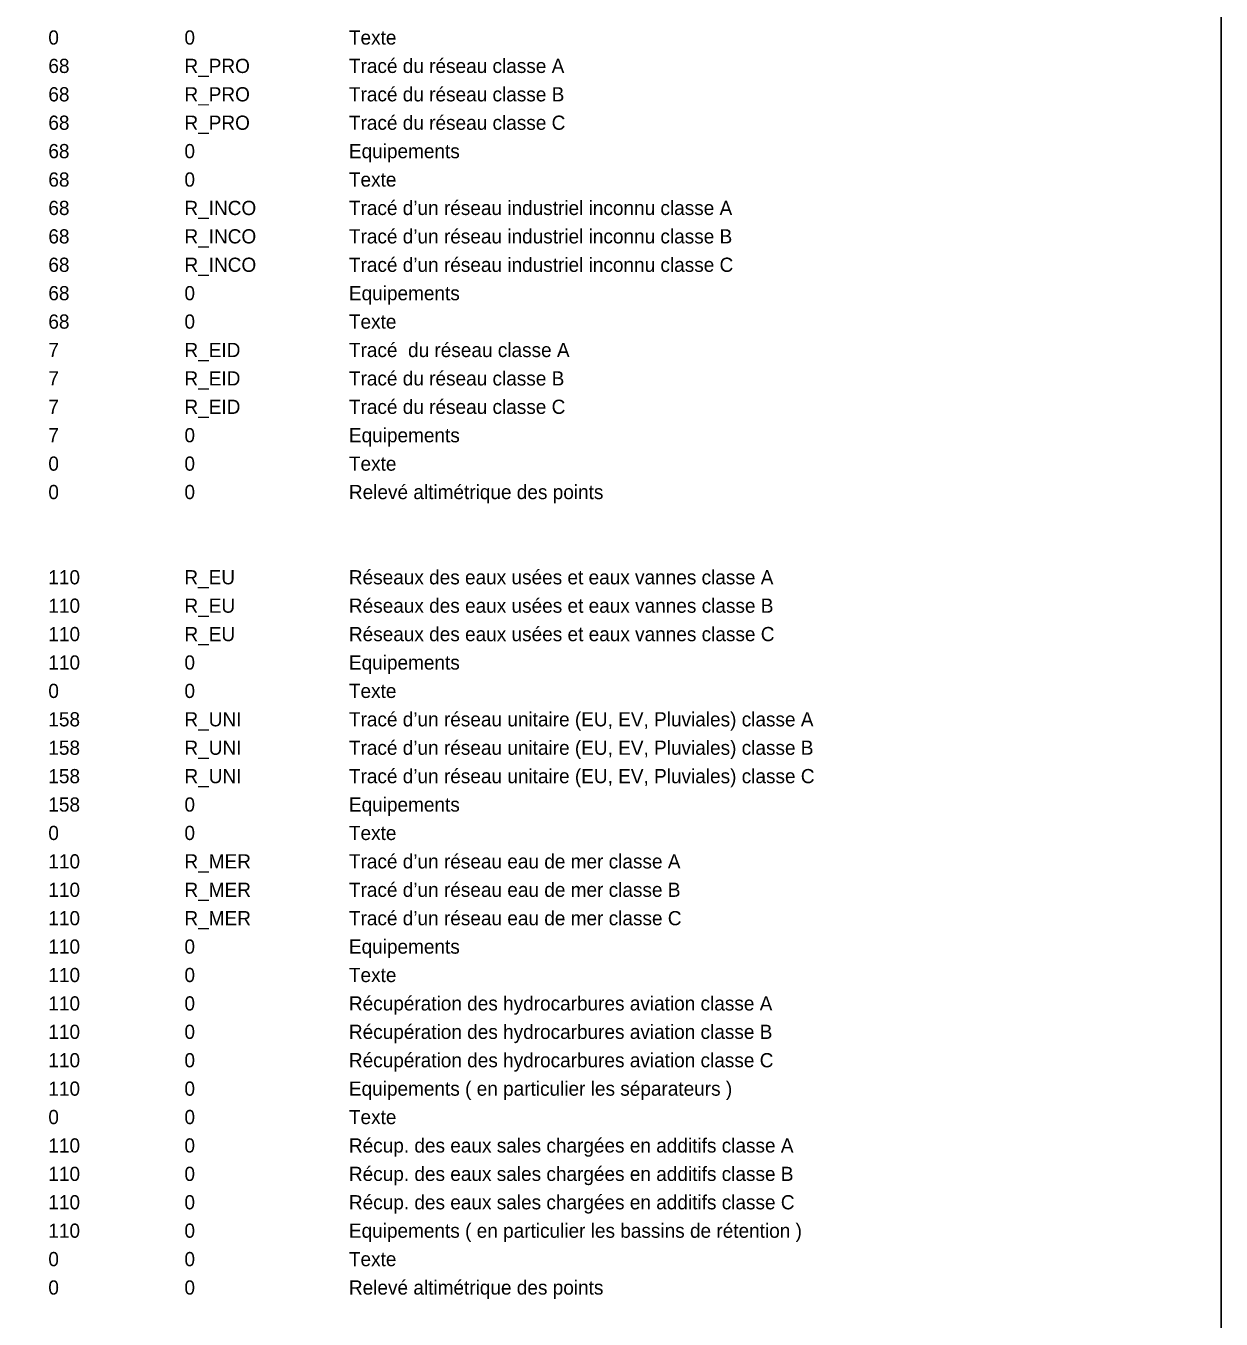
# Model space of a CAD drawing. Extents: x -60 to 214, y -380 to -21.
# Drawn here: x 72.77 to 114.84, y -201.47 to -155.95 of the extents above; entities that cross this region are included whole.
import ezdxf

# ---------------------------------------------------------------- set-up
doc = ezdxf.new("R2010")
doc.units = 0
for name, color, linetype in [('Default', 7, 'Continuous'), ('R_ES_EAU_SALE_ALT_POINT', 7, 'Continuous'), ('R_ES_EU_CANALISATION_CL_A', 7, 'Continuous'), ('R_ES_EU_CANALISATION_CL_B', 7, 'Continuous'), ('R_ES_EU_CANALISATION_CL_C', 7, 'Continuous'), ('R_ES_EU_EQUIP', 7, 'Continuous'), ('R_ES_EU_TEXTE', 7, 'Continuous'), ('R_ES_HYDROCARB_CANA_CL_A', 7, 'Continuous'), ('R_ES_HYDROCARB_CANA_CL_B', 7, 'Continuous'), ('R_ES_HYDROCARB_CANA_CL_C', 7, 'Continuous'), ('R_ES_HYDROCARB_EQUIP', 7, 'Continuous'), ('R_ES_HYDROCARB_TEXTE', 7, 'Continuous'), ('R_ES_INCENDIE_CANA_CL_A', 7, 'Continuous'), ('R_ES_INCENDIE_CANA_CL_B', 7, 'Continuous'), ('R_ES_INCENDIE_CANA_CL_C', 7, 'Continuous'), ('R_ES_INCENDIE_EQUIP', 7, 'Continuous'), ('R_ES_INCENDIE_TEXTE', 7, 'Continuous'), ('R_ES_MER_CANALISATION_CL_A', 7, 'Continuous'), ('R_ES_MER_CANALISATION_CL_B', 7, 'Continuous'), ('R_ES_MER_CANALISATION_CL_C', 7, 'Continuous'), ('R_ES_MER_EQUIP', 7, 'Continuous'), ('R_ES_MER_TEXTE', 7, 'Continuous'), ('R_ES_UNITAIRE_CANALISATION_CL_A', 7, 'Continuous'), ('R_ES_UNITAIRE_CANALISATION_CL_B', 7, 'Continuous'), ('R_ES_UNITAIRE_CANALISATION_CL_C', 7, 'Continuous'), ('R_ES_UNITAIRE_EQUIP', 7, 'Continuous'), ('R_ES_UNITAIRE_TEXTE', 7, 'Continuous'), ('R_IND_ALT_POINT', 7, 'Continuous'), ('R_IND_EAU_DEMINERALISEE_CANALISATION_CL_A', 7, 'Continuous'), ('R_IND_EAU_DEMINERALISEE_CANALISATION_CL_B', 7, 'Continuous'), ('R_IND_EAU_DEMINERALISEE_CANALISATION_CL_C', 7, 'Continuous'), ('R_IND_EAU_DEMINERALISEE_EQUIP', 7, 'Continuous'), ('R_IND_EAU_DEMINERALISEE_TEXTE', 7, 'Continuous'), ('R_IND_HYDROCARBURE_TEXTE', 7, 'Continuous'), ('R_IND_INDUS_INCON_CANALISATION_CL_A', 7, 'Continuous'), ('R_IND_INDUS_INCON_CANALISATION_CL_B', 7, 'Continuous'), ('R_IND_INDUS_INCON_CANALISATION_CL_C', 7, 'Continuous'), ('R_IND_INDUS_INCON_EQUIP', 7, 'Continuous'), ('R_IND_INDUS_INCON_TEXTE', 7, 'Continuous'), ('R_IND_PROPANE_CANALISATION_CL_A', 7, 'Continuous'), ('R_IND_PROPANE_CANALISATION_CL_B', 7, 'Continuous'), ('R_IND_PROPANE_CANALISATION_CL_C', 7, 'Continuous'), ('R_IND_PROPANE_EQUIP', 7, 'Continuous'), ('R_IND_PROPANE_TEXTE', 7, 'Continuous')]:
    doc.layers.add(name, color=color, linetype=linetype)

msp = doc.modelspace()

# ---------------------------------------------------------------- linework, layer by layer
at = {"layer": 'Default'}
msp.add_lwpolyline([(114.838, -25.727), (33.073, -25.727), (33.073, -380.216), (114.838, -380.216)], close=True, dxfattribs=at)

# ---------------------------------------------------------------- texts
at = {"layer": 'R_ES_EAU_SALE_ALT_POINT'}
for s, p in [('0 ', (73.561, -200.61)), ('0 ', (78.351, -200.61)), ('Relevé altimétrique des points ', (84.14, -200.61))]:
    msp.add_text(s, height=0.5, dxfattribs=at).set_placement(p)
at = {"layer": 'R_ES_EU_CANALISATION_CL_A'}
for s, p in [('110 ', (73.559, -175.61)), ('R_EU ', (78.348, -175.61)), ('Réseaux des eaux usées et eaux vannes classe A ', (84.138, -175.61))]:
    msp.add_text(s, height=0.5, dxfattribs=at).set_placement(p)
at = {"layer": 'R_ES_EU_CANALISATION_CL_B'}
for s, p in [('110 ', (73.561, -176.61)), ('R_EU ', (78.351, -176.61)), ('Réseaux des eaux usées et eaux vannes classe B ', (84.14, -176.61))]:
    msp.add_text(s, height=0.5, dxfattribs=at).set_placement(p)
at = {"layer": 'R_ES_EU_CANALISATION_CL_C'}
for s, p in [('Réseaux des eaux usées et eaux vannes classe C ', (84.14, -177.61)), ('110 ', (73.561, -177.61)), ('R_EU ', (78.351, -177.61))]:
    msp.add_text(s, height=0.5, dxfattribs=at).set_placement(p)
at = {"layer": 'R_ES_EU_EQUIP'}
for s, p in [('110 ', (73.561, -178.61)), ('0 ', (78.351, -178.61)), ('Equipements ', (84.14, -178.61))]:
    msp.add_text(s, height=0.5, dxfattribs=at).set_placement(p)
at = {"layer": 'R_ES_EU_TEXTE'}
for s, p in [('0', (73.561, -179.61)), ('0 ', (78.351, -179.61)), ('Texte ', (84.14, -179.61))]:
    msp.add_text(s, height=0.5, dxfattribs=at).set_placement(p)
at = {"layer": 'R_ES_HYDROCARB_CANA_CL_A'}
for s, p in [('110 ', (73.561, -190.61)), ('0 ', (78.351, -190.61)), ('Récupération des hydrocarbures aviation classe A ', (84.14, -190.61))]:
    msp.add_text(s, height=0.5, dxfattribs=at).set_placement(p)
at = {"layer": 'R_ES_HYDROCARB_CANA_CL_B'}
for s, p in [('110 ', (73.561, -191.61)), ('0 ', (78.351, -191.61)), ('Récupération des hydrocarbures aviation classe B ', (84.14, -191.61))]:
    msp.add_text(s, height=0.5, dxfattribs=at).set_placement(p)
at = {"layer": 'R_ES_HYDROCARB_CANA_CL_C'}
for s, p in [('110 ', (73.561, -192.61)), ('0 ', (78.351, -192.61)), ('Récupération des hydrocarbures aviation classe C ', (84.14, -192.61))]:
    msp.add_text(s, height=0.5, dxfattribs=at).set_placement(p)
at = {"layer": 'R_ES_HYDROCARB_EQUIP'}
for s, p in [('110 ', (73.561, -193.61)), ('0 ', (78.351, -193.61)), ('Equipements ( en particulier les séparateurs )  ', (84.14, -193.61))]:
    msp.add_text(s, height=0.5, dxfattribs=at).set_placement(p)
at = {"layer": 'R_ES_HYDROCARB_TEXTE'}
for s, p in [('0', (73.561, -194.61)), ('0 ', (78.351, -194.61)), ('Texte ', (84.14, -194.61))]:
    msp.add_text(s, height=0.5, dxfattribs=at).set_placement(p)
at = {"layer": 'R_ES_INCENDIE_CANA_CL_A'}
for s, p in [('110 ', (73.561, -195.61)), ('0 ', (78.351, -195.61)), ('Récup. des eaux sales chargées en additifs classe A ', (84.14, -195.61))]:
    msp.add_text(s, height=0.5, dxfattribs=at).set_placement(p)
at = {"layer": 'R_ES_INCENDIE_CANA_CL_B'}
for s, p in [('110 ', (73.561, -196.61)), ('0 ', (78.351, -196.61)), ('Récup. des eaux sales chargées en additifs classe B ', (84.14, -196.61))]:
    msp.add_text(s, height=0.5, dxfattribs=at).set_placement(p)
at = {"layer": 'R_ES_INCENDIE_CANA_CL_C'}
for s, p in [('110 ', (73.561, -197.61)), ('0 ', (78.351, -197.61)), ('Récup. des eaux sales chargées en additifs classe C ', (84.14, -197.61))]:
    msp.add_text(s, height=0.5, dxfattribs=at).set_placement(p)
at = {"layer": 'R_ES_INCENDIE_EQUIP'}
for s, p in [('110 ', (73.561, -198.61)), ('0 ', (78.351, -198.61)), ('Equipements ( en particulier les bassins de rétention ) ', (84.14, -198.61))]:
    msp.add_text(s, height=0.5, dxfattribs=at).set_placement(p)
at = {"layer": 'R_ES_INCENDIE_TEXTE'}
for s, p in [('0', (73.561, -199.61)), ('0 ', (78.351, -199.61)), ('Texte ', (84.14, -199.61))]:
    msp.add_text(s, height=0.5, dxfattribs=at).set_placement(p)
at = {"layer": 'R_ES_MER_CANALISATION_CL_A'}
for s, p in [('110 ', (73.561, -185.61)), ('R_MER ', (78.351, -185.61)), ('Tracé d’un réseau eau de mer classe A ', (84.14, -185.61))]:
    msp.add_text(s, height=0.5, dxfattribs=at).set_placement(p)
at = {"layer": 'R_ES_MER_CANALISATION_CL_B'}
for s, p in [('110 ', (73.561, -186.61)), ('R_MER ', (78.351, -186.61)), ('Tracé d’un réseau eau de mer classe B ', (84.14, -186.61))]:
    msp.add_text(s, height=0.5, dxfattribs=at).set_placement(p)
at = {"layer": 'R_ES_MER_CANALISATION_CL_C'}
for s, p in [('Tracé d’un réseau eau de mer classe C ', (84.14, -187.61)), ('110 ', (73.561, -187.61)), ('R_MER ', (78.351, -187.61))]:
    msp.add_text(s, height=0.5, dxfattribs=at).set_placement(p)
at = {"layer": 'R_ES_MER_EQUIP'}
for s, p in [('110 ', (73.561, -188.61)), ('0 ', (78.351, -188.61)), ('Equipements ', (84.14, -188.61))]:
    msp.add_text(s, height=0.5, dxfattribs=at).set_placement(p)
at = {"layer": 'R_ES_MER_TEXTE'}
for s, p in [('110 ', (73.561, -189.61)), ('0 ', (78.351, -189.61)), ('Texte ', (84.14, -189.61))]:
    msp.add_text(s, height=0.5, dxfattribs=at).set_placement(p)
at = {"layer": 'R_ES_UNITAIRE_CANALISATION_CL_A'}
for s, p in [('158 ', (73.561, -180.61)), ('R_UNI ', (78.351, -180.61)), ('Tracé d’un réseau unitaire (EU, EV, Pluviales) classe A ', (84.14, -180.61))]:
    msp.add_text(s, height=0.5, dxfattribs=at).set_placement(p)
at = {"layer": 'R_ES_UNITAIRE_CANALISATION_CL_B'}
for s, p in [('158 ', (73.561, -181.61)), ('R_UNI ', (78.351, -181.61)), ('Tracé d’un réseau unitaire (EU, EV, Pluviales) classe B ', (84.14, -181.61))]:
    msp.add_text(s, height=0.5, dxfattribs=at).set_placement(p)
at = {"layer": 'R_ES_UNITAIRE_CANALISATION_CL_C'}
for s, p in [('Tracé d’un réseau unitaire (EU, EV, Pluviales) classe C ', (84.14, -182.61)), ('158 ', (73.561, -182.61)), ('R_UNI ', (78.351, -182.61))]:
    msp.add_text(s, height=0.5, dxfattribs=at).set_placement(p)
at = {"layer": 'R_ES_UNITAIRE_EQUIP'}
for s, p in [('158 ', (73.561, -183.61)), ('0 ', (78.351, -183.61)), ('Equipements ', (84.14, -183.61))]:
    msp.add_text(s, height=0.5, dxfattribs=at).set_placement(p)
at = {"layer": 'R_ES_UNITAIRE_TEXTE'}
for s, p in [('0', (73.561, -184.61)), ('0 ', (78.351, -184.61)), ('Texte ', (84.14, -184.61))]:
    msp.add_text(s, height=0.5, dxfattribs=at).set_placement(p)
at = {"layer": 'R_IND_ALT_POINT'}
for s, p in [('Relevé altimétrique des points ', (84.14, -172.61)), ('0 ', (73.561, -172.61)), ('0 ', (78.351, -172.61))]:
    msp.add_text(s, height=0.5, dxfattribs=at).set_placement(p)
at = {"layer": 'R_IND_EAU_DEMINERALISEE_CANALISATION_CL_A'}
for s, p in [('7 ', (73.561, -167.61)), ('R_EID ', (78.351, -167.61)), ('Tracé  du réseau classe A ', (84.14, -167.61))]:
    msp.add_text(s, height=0.5, dxfattribs=at).set_placement(p)
at = {"layer": 'R_IND_EAU_DEMINERALISEE_CANALISATION_CL_B'}
for s, p in [('7 ', (73.561, -168.61)), ('R_EID ', (78.351, -168.61)), ('Tracé du réseau classe B ', (84.14, -168.61))]:
    msp.add_text(s, height=0.5, dxfattribs=at).set_placement(p)
at = {"layer": 'R_IND_EAU_DEMINERALISEE_CANALISATION_CL_C'}
for s, p in [('7 ', (73.561, -169.61)), ('R_EID ', (78.351, -169.61)), ('Tracé du réseau classe C ', (84.14, -169.61))]:
    msp.add_text(s, height=0.5, dxfattribs=at).set_placement(p)
at = {"layer": 'R_IND_EAU_DEMINERALISEE_EQUIP'}
for s, p in [('7 ', (73.561, -170.61)), ('0 ', (78.351, -170.61)), ('Equipements ', (84.14, -170.61))]:
    msp.add_text(s, height=0.5, dxfattribs=at).set_placement(p)
at = {"layer": 'R_IND_EAU_DEMINERALISEE_TEXTE'}
for s, p in [('0', (73.561, -171.61)), ('0 ', (78.351, -171.61)), ('Texte ', (84.14, -171.61))]:
    msp.add_text(s, height=0.5, dxfattribs=at).set_placement(p)
at = {"layer": 'R_IND_HYDROCARBURE_TEXTE'}
for s, p in [('0', (73.561, -156.61)), ('0 ', (78.351, -156.61)), ('Texte ', (84.14, -156.61))]:
    msp.add_text(s, height=0.5, dxfattribs=at).set_placement(p)
at = {"layer": 'R_IND_INDUS_INCON_CANALISATION_CL_A'}
for s, p in [('68 ', (73.561, -162.61)), ('R_INCO ', (78.351, -162.61)), ('Tracé d’un réseau industriel inconnu classe A ', (84.14, -162.61))]:
    msp.add_text(s, height=0.5, dxfattribs=at).set_placement(p)
at = {"layer": 'R_IND_INDUS_INCON_CANALISATION_CL_B'}
for s, p in [('68 ', (73.561, -163.61)), ('R_INCO ', (78.351, -163.61)), ('Tracé d’un réseau industriel inconnu classe B ', (84.14, -163.61))]:
    msp.add_text(s, height=0.5, dxfattribs=at).set_placement(p)
at = {"layer": 'R_IND_INDUS_INCON_CANALISATION_CL_C'}
for s, p in [('68 ', (73.561, -164.61)), ('R_INCO ', (78.351, -164.61)), ('Tracé d’un réseau industriel inconnu classe C ', (84.14, -164.61))]:
    msp.add_text(s, height=0.5, dxfattribs=at).set_placement(p)
at = {"layer": 'R_IND_INDUS_INCON_EQUIP'}
for s, p in [('68 ', (73.561, -165.61)), ('0 ', (78.351, -165.61)), ('Equipements ', (84.14, -165.61))]:
    msp.add_text(s, height=0.5, dxfattribs=at).set_placement(p)
at = {"layer": 'R_IND_INDUS_INCON_TEXTE'}
for s, p in [('68 ', (73.561, -166.61)), ('0 ', (78.351, -166.61)), ('Texte ', (84.14, -166.61))]:
    msp.add_text(s, height=0.5, dxfattribs=at).set_placement(p)
at = {"layer": 'R_IND_PROPANE_CANALISATION_CL_A'}
for s, p in [('68 ', (73.561, -157.61)), ('R_PRO ', (78.351, -157.61)), ('Tracé du réseau classe A ', (84.14, -157.61))]:
    msp.add_text(s, height=0.5, dxfattribs=at).set_placement(p)
at = {"layer": 'R_IND_PROPANE_CANALISATION_CL_B'}
for s, p in [('68 ', (73.561, -158.61)), ('R_PRO ', (78.351, -158.61)), ('Tracé du réseau classe B ', (84.14, -158.61))]:
    msp.add_text(s, height=0.5, dxfattribs=at).set_placement(p)
at = {"layer": 'R_IND_PROPANE_CANALISATION_CL_C'}
for s, p in [('68 ', (73.561, -159.61)), ('R_PRO ', (78.351, -159.61)), ('Tracé du réseau classe C ', (84.14, -159.61))]:
    msp.add_text(s, height=0.5, dxfattribs=at).set_placement(p)
at = {"layer": 'R_IND_PROPANE_EQUIP'}
for s, p in [('68 ', (73.561, -160.61)), ('0 ', (78.351, -160.61)), ('Equipements ', (84.14, -160.61))]:
    msp.add_text(s, height=0.5, dxfattribs=at).set_placement(p)
at = {"layer": 'R_IND_PROPANE_TEXTE'}
for s, p in [('68 ', (73.561, -161.61)), ('0 ', (78.351, -161.61)), ('Texte ', (84.14, -161.61))]:
    msp.add_text(s, height=0.5, dxfattribs=at).set_placement(p)

doc.saveas('drawing.dxf')
